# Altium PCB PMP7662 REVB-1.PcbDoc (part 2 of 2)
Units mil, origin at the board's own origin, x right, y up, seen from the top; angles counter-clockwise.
Board outline 7874.02 x 3937.01 mil, 2 copper layers (Top Layer, Bottom Layer), stack 62 mil thick; 165 components, 77 nets, 359 pads, 90 vias.
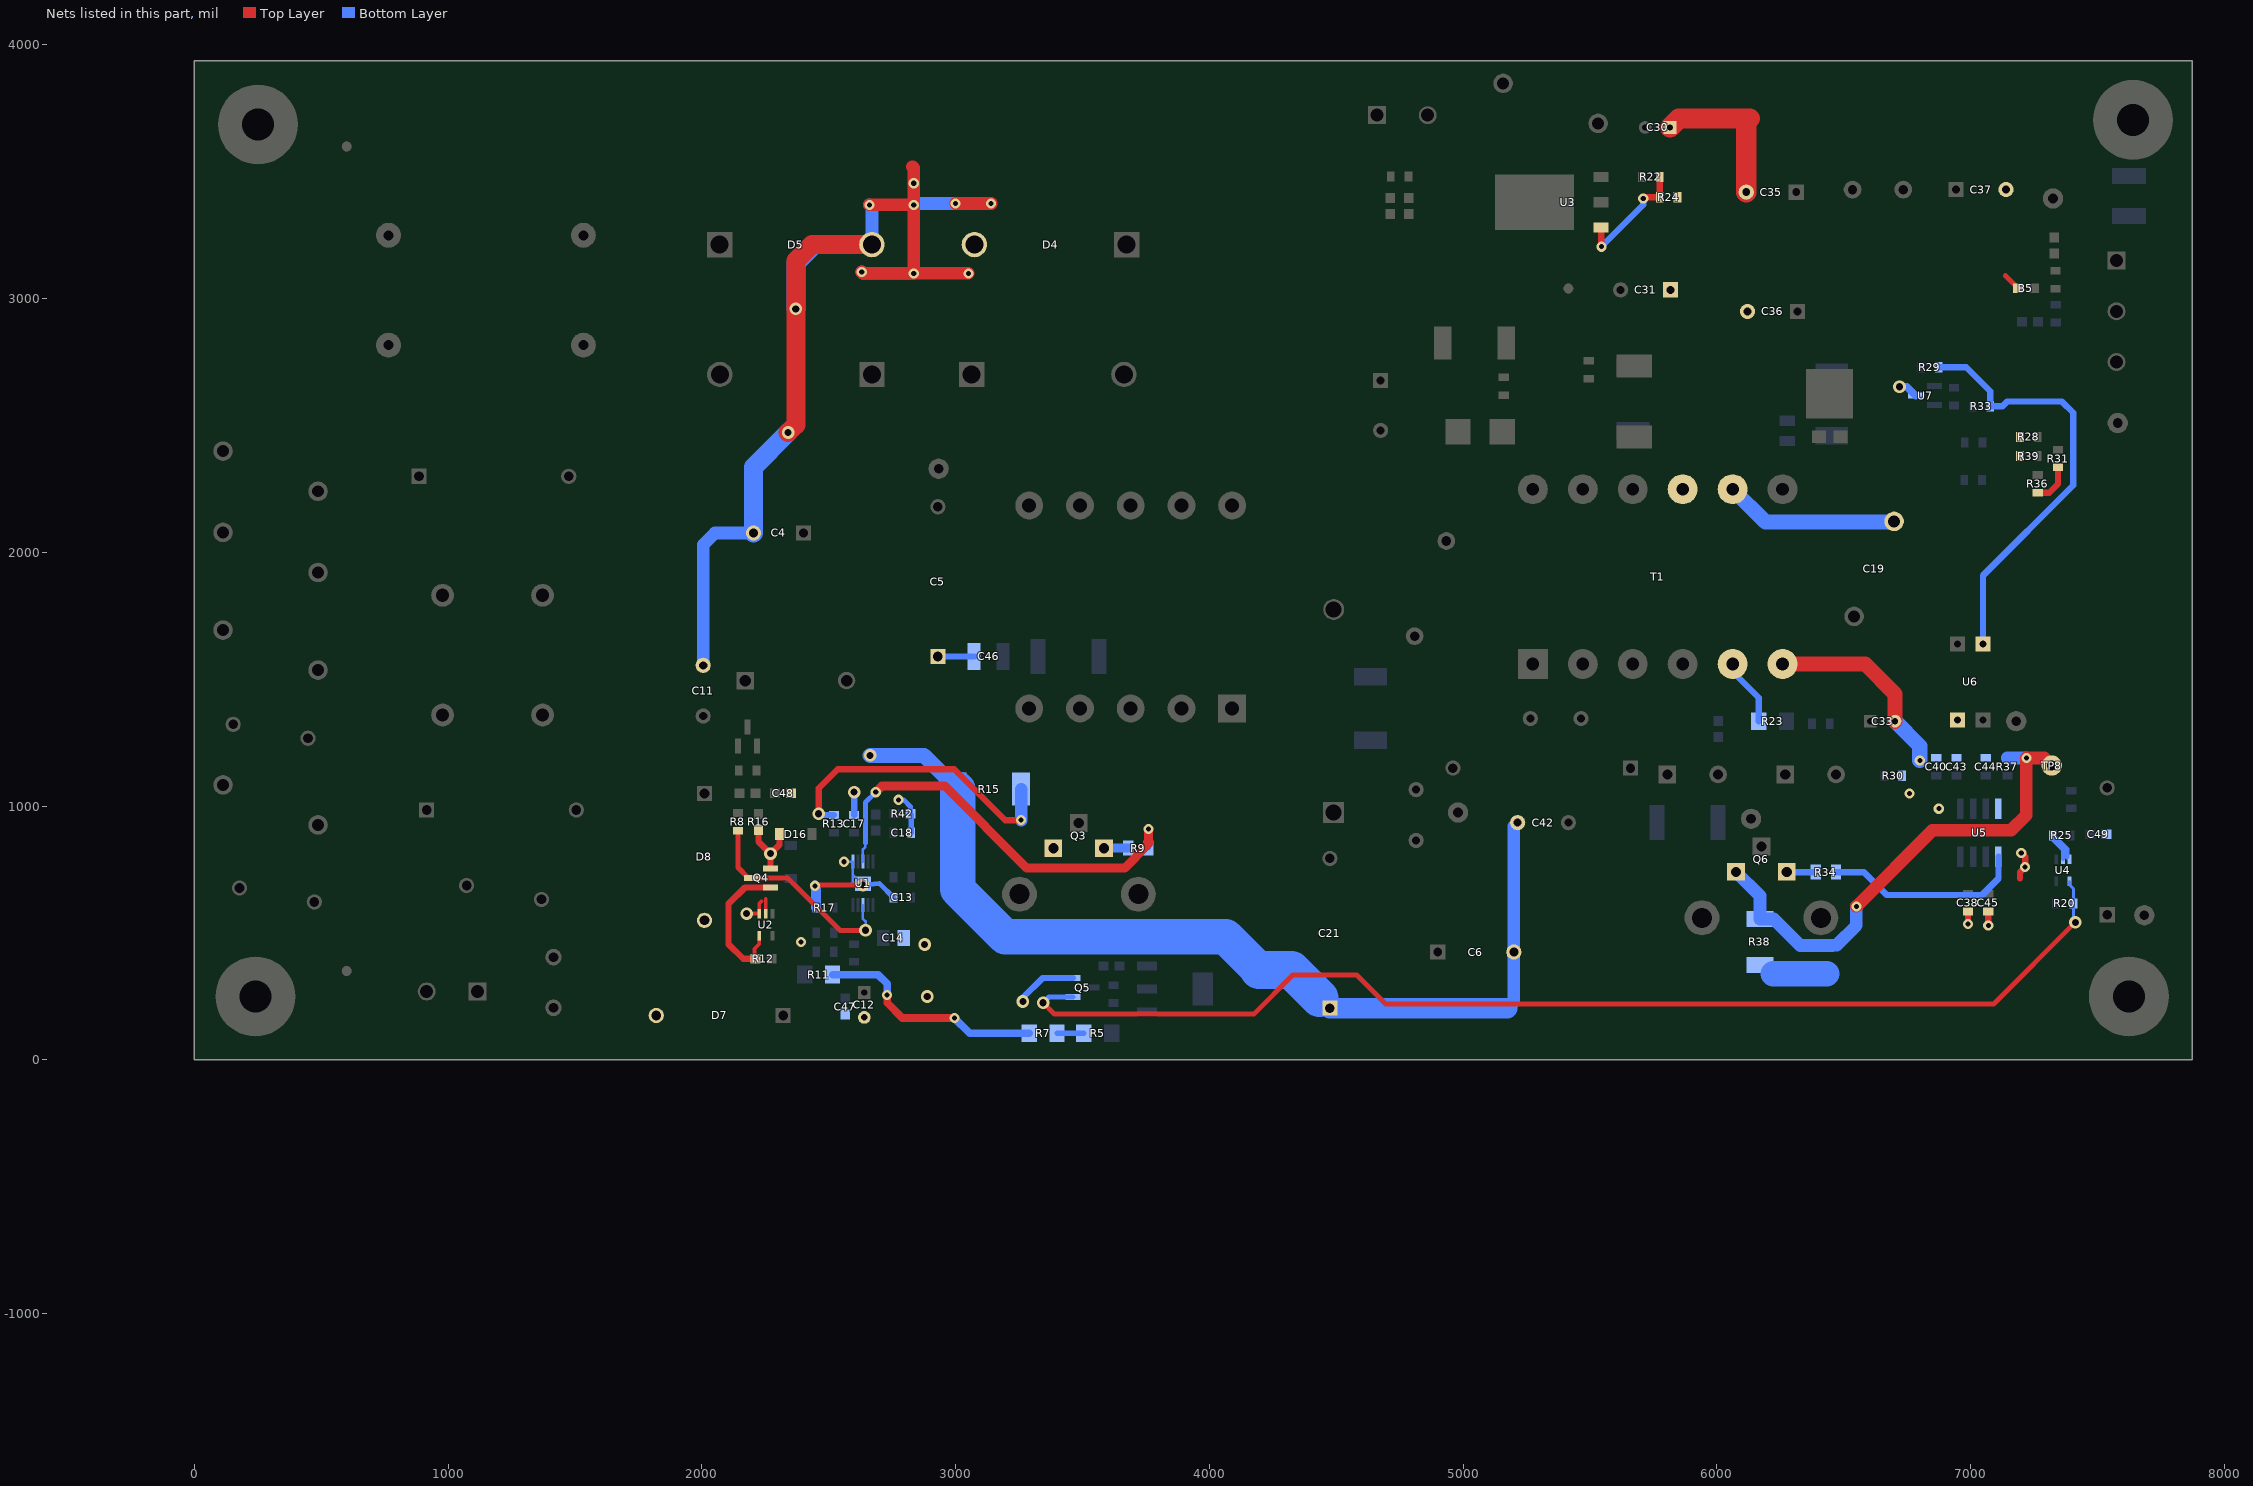
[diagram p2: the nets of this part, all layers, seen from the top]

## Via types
v1: diameter 40, hole 20, Top Layer to Bottom Layer, tented both sides, 69 vias
v2: diameter 50, hole 28, Top Layer to Bottom Layer, tented both sides, 21 vias

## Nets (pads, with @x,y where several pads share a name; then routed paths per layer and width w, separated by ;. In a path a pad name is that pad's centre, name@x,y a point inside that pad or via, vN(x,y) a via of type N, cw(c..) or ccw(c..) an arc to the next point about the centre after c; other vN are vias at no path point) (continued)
NetQ3_1: Q3.1 R9.2 | length 95.4
  Bottom Layer w35: Q3.1@3585,834.1 3585.9,835 R9.2@3680,835
NetQ3_3: Q3.3 R13.2 R15.1 | length 1196
  Top Layer w25: v2(2460,970) 2460,1070 2535,1145 2995,1145 3195,945 v1(3258,945)
  Bottom Layer w25: v2(2460,970) 2465,965 R13.2@2520,965
  Bottom Layer w50: v1(3258,945) R15.1@3258,1067
NetQ4_1: Q4.1 R12.2 U2.4 | length 578.1
  Top Layer w10: U2.4@2224.7,490.6 U2.4@2225.9,489.4
  Top Layer w15: R12.2@2207,398 2207,438 2225.9,456.9 U2.4@2225.9,489.4
  Top Layer w25: R12.2@2207,398 2163,398 2105,456 2105,615 2169.6,679.6 Q4.1@2270.4,679.6
NetQ4_3: Q4.3 R8.2 U1.3 | length 854.5
  Top Layer w20: R8.2@2142,903 2142,758 2183,717 Q4.3@2195.6,717 2338,717 2545,510 2644,510 v2(2645,511)
  Bottom Layer w10: U1.3@2634.4,610 2634.4,556 2645,545.4 v2(2645,511)
NetQ5_1: Q5.1 R20.2 U4.4 | length 4629.7
  Top Layer w20: v2(3345,225) 3390,180 4175,180 4330,335 4580,335 4695,220 7091,220 v2(7413,542)
  Bottom Layer w12: U4.4@7390.1,703.4 7390.1,689.9 7406,674 R20.2@7406,617 7406,549 v2(7413,542)
  Bottom Layer w20: v2(3345,225) 3367.6,247.6 Q5.1@3462.6,247.6
NetQ6_1: Q6.1 R34.2 | length 114.7
  Bottom Layer w25: Q6.1@6275.75,741.1 6276.85,740 R34.2@6390,740
NetQ6_3: Q6.3 R37.2 R38.1 TP8.1 | length 1987.1
  Top Layer w50: v1(6550,605) 6850,905 7160,905 7220,965 v1(7220,1190) 7290,1190 TP8.1@7320,1160
  Bottom Layer w50: Q6.3@6075.75,741.1 6170,646.85 R38.1@6170,555.55 6224.45,555.55 6328.9,451.1 6455.11,451.1 6455.74,451.73 6471.73,451.73 6550,530 v1(6550,605) ; R37.2@7145,1190 v1(7220,1190)
NetR5_2: R5.2 R7.1 | length 105
  Bottom Layer w20: R7.1@3400,105 R5.2@3505,105
NetR7_2: R7.2 R11.1 | length 914.6
  Top Layer w30: v1(2730,255) 2730,225 2790,165 v1(2995,165)
  Bottom Layer w30: R11.1@2515,336 2694,336 2730,300 v1(2730,255) ; v1(2995,165) 3055,105 R7.2@3290,105
NetR9_1: R9.1 U1.8 | length 1688.5
  Top Layer w35: v1(2685,1055) 2710,1080 2957,1080 3281,756 3666,756 3760,850 v1(3760,910)
  Bottom Layer w10: U1.8@2634.4,781 2634.4,829.4 2644,839 2644,855
  Bottom Layer w20: 2644,855 2644,1014 v1(2685,1055) ; R9.1@3760,835 v1(3760,910)
NetR22_1: R22.1 R24.1 U3.1 | length 480.8
  Top Layer w25: U3.1@5544,3280 5544,3206 v1(5545,3205) ; v1(5710,3395) 5715,3400 R24.1@5775,3400 R22.1@5775,3480
  Bottom Layer w25: v1(5545,3205) 5710,3370 v1(5710,3395)
NetR23_1: R23.1 T1.5 | length 237.5
  Bottom Layer w25: T1.5@6062.4,1530 6165,1427.4 R23.1@6165,1335
NetR29_1: R29.1 R33.1 U6.1 | length 1712.8
  Bottom Layer w25: R29.1@6875,2730 6983,2730 7078,2635 R33.1@7078,2576 7126,2576 7145,2595 7360,2595 7405,2550 7405,2265 7049,1909 U6.1@7049,1639.5
NetR31_1: R31.1 R36.1 | length 159.5
  Top Layer w25: R36.1@7265,2235 7310,2235 7345,2270 R31.1@7345,2335
NetR34_1: R34.1 U5.5 | length 790.2
  Bottom Layer w25: R34.1@6470,740 6580,740 6670,650 7045,650 7110,715 U5.5@7110,801
PGND: C4.2 C5.1 C6.2 C11.1 C12.2 C13.1 C14.2 C17.1 C18.1 C21.1 C33.2 C38.2 C40.1 C42.2 C43.2 C44.2 C45.1 C46.2 C47.2 C48.2 C49.2 D4.2 D5.2 D7.2 D8.2 D16.2 Q4.2 Q5.2 R15.2 R16.2 R17.2 R25.2 R30.2 R38.2 R42.1 T1.6 U1.6 U1.11 U2.2 U2.3 U4.2 U4.3 U5.4 U6.3 | length 11379.2
  Top Layer w15: v2(2176.4,576.4) U2.3@2225.9,576.4 2225.9,615.9 2235,625 ; U2.2@2251.9,576.4 2251.9,634.1
  Top Layer w20: v1(2445,686) 2448.5,689.5 v2(2634.8,689.5)
  Top Layer w25: R16.2@2223,903 2223,860.4 v2(2270.4,813) ; Q4.2@2270.4,754.4 v2(2270.4,813) ; D16.2@2305.53,890 2305.53,848.13 v2(2270.4,813) ; v1(6990,535) C38.2@6990,585 ; v1(7070,530) C45.1@7070,585 ; 7195,715 7195,740 v1(7215,760) 7215,800 v1(7200,815)
  Top Layer w50: v1(2630,3105) 2635,3100 v1(2835,3100) ; v1(2660,3370) v1(2835,3370) ; 2830,3520 2835,3515 v1(2835,3455) v1(2835,3370) ; v1(3000,3375) v1(3140,3375) ; v1(3050,3100) v1(2835,3100) ; v1(2835,3100) v1(2835,3370)
  Top Layer w60: T1.6@6259.25,1560 6585,1560 6702.5,1442.5 C33.2@6702.5,1335
  Top Layer w75: v2(2340,2473) 2370,2503 v2(2370,2960) 2370,3150 2433.31,3213.31 D5.2@2670,3213.31
  Bottom Layer w10: v1(2560,781) U1.6@2595,781 2595,694.5 ; 2595,729.3 v2(2634.8,689.5)
  Bottom Layer w15: U4.2@7364.1,790.4 7364.1,830.9
  Bottom Layer w20: 2595,694.5 v2(2634.8,689.5) 2700.5,694.5 C13.1@2755,640 ; 2755,1200 2775,1180 ; v1(2775,1025) 2795,1025 2821.5,998.5 R42.1@2821.5,970 2825,966.5 C18.1@2825,895 ; 7364.1,830.9 7325,870 R25.2@7325,885 7380,830 7380,800.5
  Bottom Layer w25: v2@2270,813 v2(2270.4,813) ; C17.1@2600,965 v2(2600,1055) ; C5.1@2930,1590 C46.2@3072.91,1590 ; v2@3265,245 3342.4,322.4 Q5.2@3462.6,322.4 ; v1(6875,990) v1@6875,995
  Bottom Layer w40: v1(2445,686) 2450,681 R17.2@2450,600
  Bottom Layer w50: C11.1@2005,1555 2005,2030 2051.6,2076.6 C4.2@2203.6,2076.6 ; v1(2630,3105) 2635,3100 v1(2835,3100) ; v1(2660,3370) 2670,3360 D5.2@2670,3213.31 ; v1(2835,3370) 2840,3375 v1(3000,3375) ; 5174,204 5200,230 C6.2@5200,425 5200,920 C42.2@5215,935
  Bottom Layer w60: v2(2663,1200) 2755,1200 2875,1200 R15.2@3008,1067 ; 6443.55,338.45 6448,334 ; C33.2@6702.5,1335 6800,1237.5 v1(6800,1180)
  Bottom Layer w75: C4.2@2203.6,2076.6 2203.6,2336.6 v2(2340,2473) ; v2(2370,2960) 2370,3140 2443.31,3213.31 D5.2@2670,3213.31
  Bottom Layer w80: C21.1@4475,204 5174,204
  Bottom Layer w100: 6223,340 6433.55,340
  Bottom Layer w140: R15.2@3008,1067 3008,671.78 3194.78,485 4065,485 4195,355
  Bottom Layer w150: 4195,355 4324,355 4434.5,244.5
  other v1: 2390,465 6760,1050
  other v2: 3265,230 2888,250 2878,455
PWRGND: B5.1 C19.2 C30.1 C31.1 C35.2 C36.2 C37.2 R24.2 R28.2 R39.2 T1.8 T1.9 U7.3 | length 1441.5
  Top Layer w20: 7138,3090.5 B5.1@7186.5,3042
  Top Layer w80: C30.1@5815.5,3675 5850.5,3710 6130,3710 6116,3696 C35.2@6116,3420
  Bottom Layer w30: v2(6720,2653) 6748.6,2653 U7.3@6783.6,2618
  Bottom Layer w60: T1.8@6062.4,2248.98 6191.38,2120 C19.2@6679,2120
pads on no net: FID1.1 FID2.1 FID3.1 FID4.1 FID5.1 FID6.1 H1.1 H4.1 HT1.1 HT1.2 HT2.1 HT2.2 L1.1 L1.2 L1.9 L1.10 LBL1.0 Logo1.0 T1.2 T1.3 U2.1 U4.1 U5.8

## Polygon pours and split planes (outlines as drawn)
PWRGND on Top Layer "Bottom Layer-No Net 7" (solid, pour order 101): 5800,3600 5775,3625 5775,3780 5810,3815 7085,3815 7230,3670 7230,3130 7200,3100 7200,2850 7145,2795 7150,2790 7150,2610 7225,2535 7225,1770 7155,1700 6850,1700 6775,1775 6775,2450 6650,2575 6650,3585 6585,3650 6000,3650 5950,3600
PGND on Top Layer "Top Layer-No Net 11" (solid, remove dead copper, pour order 130): 2710,1260 2775,1195 2775,1055 2815,1055 2925,945 2925,125 2895,95 1800,95 1775,120 1775,300 1955,480 1955,845 2370,1260
NetD1_2 on Top Layer "Top Layer-No Net 10" (hatched 90Degree grid 5 track 8, remove dead copper, pour order 97): 3220,1160 3170,1210 3170,1415 3195,1440 3775,1440 3790,1425 3790,1320 3810,1300 4205,1300 4255,1350 4255,1360 4252,1889.69 4282,1918.2 4306,1941 4553,1941 4586,1909.65 4604,1892.54 4604,1714.87 4559,1672.12 4554,1676.87 4425,1675 4390,1640 4390,1265 4285,1160
NetB4_1 on Top Layer "Top Layer-No Net 2" (solid, remove dead copper, pour order 70): 5515,3455 5720,3455 5730,3465 5730,3545 5730,3695 5720,3705 5690,3705 5680,3695 5680,3655 5680,3550 5675,3545 5650,3520 5545,3520 5510,3520 5505,3515 5505,3460 5510,3455 5515,3455
NetD1_2 on Top Layer "Top Layer-No Net 22" (hatched 90Degree grid 8 track 8, remove dead copper, pour order 100): 3440,1025 3520,1025 3520,920 3450,920 3450,1025
NetD2_2 on Top Layer "Top Layer-No Net 14" (solid, pour order 118): 3510,3480 3510,2530 3555,2485 4170,2485 4205,2520 4225,2540 4225,3215 4225,3495 4115,3605 4075,3645 3690,3645 3590,3645 3525,3580 3510,3565 3510,3470
PGND on Top Layer "Top Layer-No Net 13" (solid, pour order 116): 2522.28,3075.51 3210.51,3075.51 3215,3080 3210,3085 3210,3380 3210,3400 3150,3460 3125,3485 2650,3485 2545,3485 2515,3455 2522.28,3447.72 2522.28,3075.51
NetB5_2 on Top Layer "Top Layer-No Net 12" (solid, pour order 114): 7235,3075 7235,2990 7260,2965 7455,2965 7460,2970 7475,2985 7475,3025 7475,3060 7455,3080 7450,3085 7265,3085 7245,3085 7235,3075
PGND on Top Layer "Top Layer-No Net 5" (hatched 90Degree grid 5 track 8, remove dead copper, pour order 107): 6756.5,735 6762,735 6905,865 7009.5,865 7202,865 7218.5,850 7235,835 7235,675 7235,515 7163.5,450 7152.5,440 6789.5,440 6756.5,440 6740,455 6740,725 6751,725 6762,735
PGND on Top Layer "Top Layer-No Net 4" (hatched 90Degree grid 5 track 8, remove dead copper, pour order 106): 6805,950 7135,950 7150,950 7180,980 7180,1155 7180,1180 7150,1210 7135,1225 6795,1225 6775,1225 6720,1170 6715,1165 6715,1030 6715,982.48 6747.48,950 6795,950
NetC3_1 on Top Layer "Top Layer-No Net 3" (solid, pour order 103): 5130,1485 5130,1645 5165,1680 5320,1680 5325,1680 5360,1645 5355,1640 5355,1440 5355,1295 5150,1090 5070,1010 5070,920 5070,445 4995,370 4985,360 4830,360 4725,360 4515,570 4425,660 4425,990 4425,1005 4460,1040 4465,1045 4625,1045 4670,1045 4713,1002 4715,1000 4715,810 4715,785 4750,750 4755,745 4835,745 4850,745 4875,770 4875,1260 4875,1280 4905,1310 4910,1315 4955,1315 4960,1315 5130,1485
NetC35_1 on Top Layer "Bottom Layer-No Net 2" (solid, pour order 88): 6575,2525 6570,2530 6345,2530 6290,2530 6245,2575 6225,2595 6225,2780 6225,3525 6275,3575 6505,3575 6550,3575 6575,3550 6575,3380 6575,2535 6570,2530
NetC34_2 on Top Layer "Top Layer-No Net 1" (solid, pour order 85): 6209.85,2150 6331.12,2150 6530,2349.06 6530,2392.75 6530,2475.29 6520.3,2485 6389.33,2485 6224.4,2485 6205,2465.58 6209.85,2460.72 6209.85,2198.55 6209.85,2150
PWRGND on Top Layer "Top Layer-No Net" (solid, pour order 82): 5840,2145 6130,2145 6150,2165 6150,2260 6150,3450 6125,3475 5855,3475 5850,3475 5825,3450 5825,3135 5825,3130 5770,3075 5770,2960 5770,2875 5820,2825 5820,2555 5820,2365 5785,2330 5785,2195 5785,2170 5810,2145 5840,2145
NetD3_2 on Top Layer "Top Layer-No Net 10" (solid, remove dead copper, pour order 91): 1350,3463.39 1350,3221.86 1350,3192.88 1387.85,3154.23 1402.04,3139.74 1685.91,3139.74 1865.7,3139.74 1936.67,3067.28 1936.67,2869.23 1936.67,2564.52 1939.13,2562.01 1940.73,2563.64 2218.53,2563.64 2218.53,3219.8 2230,3231.52 2230,3410.25 2230,3477.88 2163.76,3545.51 2149.57,3560 1614.95,3560 1406.77,3560 1387.85,3540.68 1354.73,3506.86 1354.73,3453.73
NetC3_1 on Top Layer "Top Layer-No Net 10" (solid, remove dead copper, pour order 99): 4309,760 4650,760 4672,782 4715,825 4715,868 4715,1000 4660,1055 4639,1076 4446,1076 4385,1076 4324,1015 4311,1002 4311,768.64
NetC4_1 on Top Layer "Top Layer-No Net 10" (hatched 90Degree grid 5 track 8, remove dead copper, pour order 93): 3750.92,1990 3771.69,2015 3780,2025 3780,2310 3725.99,2375 3721.84,2380 2492.1,2380 2371.62,2235 2355,2215 2355,2005 2370,1990
PGND on Top Layer "Bottom Layer-No Net" (hatched 90Degree grid 5 track 8, remove dead copper, pour order 109): 2830,285 3290,285 3305,270 3305,215 3300,210 3295,205 3235,205 3210,205 3200,215 3160,215 2807,215 2801,221 2795,227 2795,260 2795,275 2805,285 2830,285
NetD3_2 on Top Layer "Top Layer-No Net 17" (solid, pour order 128): 1370,3055 1340,3085 1340,3095 1340,3182.88 1350,3192.88 1362.88,3180 1775,3180 1830,3180 1900,3110 1905,3105 1905,2785 1900,2785 1625,3060 1620,3055 1370,3055
NetD2_2 on Top Layer "Top Layer-No Net 18" (solid, pour order 132): 3505,3555 3505,3825 3565,3885 3570,3890 4225,3890 4235,3890 4340,3785 4340,2570.69 4340,2560 4270,2490 4265,2485 4170,2485 4105,2485 4045,2545 3865,2725 3865,3315 3745,3315 3505,3555
PGND on Top Layer "Top Layer-No Net 19" (solid, pour order 133): 2522.28,3447.72 2525,3450.43 2525,3855 2525,3875 2555,3905 3090,3905 3180,3905 3205,3880 3221.56,3863.44 3221.56,3370.79 2579.21,3370.79 2530,3420 2520,3430 2520,3470
NetD3_2 on Top Layer "Top Layer-No Net 20" (solid, pour order 134): 2230,3477.88 2230,3825 2155,3900 2150,3905 1375,3905 1355,3905 1325,3875 1340,3860 1340,3180 2210,3180 2215,3185 2230,3200 2230,3469.79
NetC4_1 on Top Layer "Top Layer-No Net 21" (solid, pour order 137): 2522.6,2562.01 2522.6,2467.4 2525,2465 2560,2500 3310,2500 3310,2847.5 3303.45,2854.05 3302.5,2855 2515.32,2855 2515.32,2539.68 2555,2500
NetD1_2 on Top Layer "Top Layer-No Net 23" (solid, pour order 75): 3370,930 3605,930 3605,1125 3605,1126 3660,1181 3655,1176 3370,1176 3310,1176 3370,1116 3370,1115
PGND on Top Layer "Top Layer-No Net 24" (solid, pour order 80): 2330,2515 2405,2515 2405,2485 2240,2320 2240,2080 2225,2065 2180,2065 2165,2080 2165,2350
NetD12_1 on Top Layer "Top Layer-No Net 25" (solid, pour order 78): 5735,2335 5785,2385 5785,2395 5785,2495 5780,2500 5760,2520 5755,2525 5600,2525 5575,2500 5575,2240 5575,2215 5600,2190 5605,2185 5700,2185 5710,2185 5735,2210
NetC27_1 on Top Layer "Top Layer-No Net 26" (solid, pour order 81): 5475,2725 5530,2725 5615,2640 5630,2640 5740,2640 5775,2675 5775,2810 5735,2850 5735,2870 5735,3100 5755,3120 5790,3155 5790,3205 5790,3360 5720,3430 5515,3430 5515,2945 5505,2935 5475,2905 5475,2880
NetD3_2 on Bottom Layer "Bottom Layer-No Net 16" (solid, remove dead copper, pour order 115): 1915,2565 2220,2565 2220,3500 2150,3570 1380,3570 1350,3540 1350,3195 1400,3145 1865,3145 1915,3095
NetD3_2 on Bottom Layer "Bottom Layer-No Net 19" (solid, remove dead copper, pour order 121): 1350,3220 1350,3105 1375,3080 1900,3080 1935,3115 1935,3180 1845,3270 1665,3270 1625,3310 1440,3310
NetD3_2 on Bottom Layer "Bottom Layer-No Net 22" (solid, pour order 127): 1615,3080 1630,3080 1950,2765 2115,2765 2115,3135 2020,3230 1615,3230
NetD2_2 on Bottom Layer "Top Layer-No Net 10" (solid, remove dead copper, pour order 92): 655,3165 690,3130 835,3130 875,3170 875,3230 1360,3715 3215,3715 3510,3420 3510,2530 3555,2485 3800,2485 3875,2560 3860,2575 3860,3580 3535,3905 1235,3905 655,3325
PGND on Bottom Layer "Bottom Layer-No Net 9" (solid, remove dead copper, pour order 105): 6705,925 6740,890 6740,200 6810,130 7195,130 7610,545 7610,1300 7515,1395 6890,1395 6705,1210
PGND on Bottom Layer "Bottom Layer-No Net" (solid, remove dead copper, pour order 102): 2495,665 2480,650 2480,590 2465,575 2425,575 2405,555 2405,410 2400,405 2355,405 2345,395 2345,280 2355,270 2505,270 2510,265 2510,205 2525,190 2735,190 2770,225 2770,490 2870,590 2870,765 2820,815 2820,995 2810,1005 2755,1005 2745,1015 2745,1050 2755,1060 2805,1060 2910,955 2910,590 2935,565 2935,130 2900,95 1790,95 1775,110 1775,300 1955,480 1955,858 2357,1260 2700,1260 2730,1230 2730,1165 2720,1155 2495,1155 2475,1135 2475,790 2545,720 2715,720 2725,710 2725,675 2715,665
PGND on Bottom Layer "Top Layer-No Net 10" (solid, remove dead copper, pour order 94): 3080,1005 3125,1050 3125,1635 3070,1690 2870,1690 2825,1645 2825,1090 2910,1005
PGND on Bottom Layer "Bottom Layer-No Net 28" (solid, pour order 140): 2635,1260 2865,1260 2880,1245 2880,1165.17 2870,1155 2635,1155 2625,1165 2625,1250
NetB6_1 on Bottom Layer "Bottom Layer-No Net 5" (solid, pour order 95): 6680,3575 6980,3575 7030,3525 7030,3000 7050,2980 7205,2980 7220,2965 7220,2870 7175,2825 6750,2825 6650,2925 6655,2930 6655,3550
NetB5_2 on Bottom Layer "Bottom Layer-No Net 15" (solid, pour order 113): 7645,2915 7700,2970 7695,3325 7675,3345 7420,3345 7380,3305 7380,3115 7300,3035 7300,2975 7315,2960 7475,2960 7520,2915
NetC7_2 on Bottom Layer "Bottom Layer-No Net 31" (solid, pour order 90): 235,515 315,435 315,215 275,175 145,175 50,270 50,2495 75,2520 205,2520 235,2490
NetD2_2 on Bottom Layer "Bottom Layer-No Net 18" (solid, pour order 119): 3555,2485 4170,2485 4225,2540 4225,3495 4075,3645 4055,3645 3590,3645 3525,3580 3515,3570 3515,3285 3515,2521.5 3551.5,2485 3555,2485
PGND on Bottom Layer "Bottom Layer-No Net 17" (solid, pour order 117): 2515,3455 2515,3085 2530,3070 3210,3070 3216.05,3070 3221.56,3075.51 3225,3078.95 3225,3385 3125,3485 2545,3485 2515,3455
NetB3_1 on Bottom Layer "Bottom Layer-No Net 14" (solid, pour order 112): 5950,1275 6055,1275 6080,1275 6100,1255 6115,1240 6115,1025 6115,1020 6165,970 6185,950 6185,905 6185,850.35 6175.75,841.1 6174.65,840 6135,840 6120,840 6090,870 5990,870 5955,870 5925,900 5920,905 5920,1250 5920,1265 5930,1275 5950,1275
NetB3_2 on Bottom Layer "Bottom Layer-No Net 13" (solid, pour order 111): 5935,1325 6055,1325 6060,1325 6070,1335 6070,1360 6070,1361.42 5960,1471.42 5960,1640 5940,1660 5925,1675 5840,1675 5800,1675 5775,1650 5775,1520 5775,1450 5885,1340 5900,1325 5925,1325
NetB6_2 on Bottom Layer "Bottom Layer-No Net 6" (solid, pour order 98): 7250,2938.54 7245,2933.54 7245,2770 7245,2705 7275,2675 7550,2675 7655,2675 7680,2700 7680,2840 7680,2845 7665,2860 7655,2870 7570,2870 7530,2870 7465,2935 7461.46,2938.54 7250,2938.54
NetC35_1 on Bottom Layer "Bottom Layer-No Net 4" (solid, pour order 89): 6310,2610 6545,2610 6550,2610 6575,2635 6570,2640 6570,2985 6570,3005 6535,3040 6320,3040 6250,3040 6225,3015 6225,2660 6225,2635 6250,2610 6315,2610
PGND on Bottom Layer "Bottom Layer-No Net 1" (solid, pour order 73): 4330,115 4555,115 4565,115 4595,145 4595,320 4595,330 4560,365 4525,400 4380,400 4290,310 4290,155 4290,154 4330,114
PGND on Bottom Layer "Top Layer-No Net 10" (solid, remove dead copper, pour order 96): 2835,1525 3080,1525 3100,1545 3100,1830 3035,1895 2270,1895 2270,2135 2240,2165 2115,2165 2090,2140 2090,1765 2110,1745 2785,1745 2825,1705 2825,1535
NetQ3_3 on Bottom Layer "Bottom Layer-No Net 23" (solid, pour order 129): 3310,870 3420,870 3420,800 3420,795 3310,795 3310,870
NetD2_2 on Bottom Layer "Bottom Layer-No Net 11" (solid, pour order 131): 3535,3905 3550,3890 4205,3890 4235,3890 4325,3800 4340,3785 4340,2965 4340,2560 4265,2485 4260,2490 4125,2490 4015,2490 3815,2690 3815,3405 3815,3480 3530,3765 3535,3770 3535,3890
NetC4_1 on Bottom Layer "Bottom Layer-No Net 24" (solid, pour order 135): 2522.6,2555 2525,2552.6 2525,2425 3220,2425 3225,2430 3225,2560 2524.61,2560 2522.6,2562.01
NetC4_1 on Bottom Layer "Bottom Layer-No Net 25" (solid, pour order 136): 3188.06,2857.28 3190.34,2855 3277.5,2855 3302.5,2855 3307.5,2850 3307.5,2430 3202.5,2430 3197.5,2425 3188.06,2434.44 3188.06,2857.28
PGND on Bottom Layer "Bottom Layer-No Net 26" (solid, pour order 138): 2515,3085 2515,3015 2515,3033.31 2523.31,3025 2785,3025 3221.69,3025 3225,3028.31 3225,3078.95
PGND on Bottom Layer "Bottom Layer-No Net 27" (solid, pour order 139): 3180,3025 3291.69,3025 3295,3028.31 3300,3033.31 3300,3315 3230,3385 3225,3385 3199,3385 3194,3390 3180,3376 3180,3030
PGND on Bottom Layer "Bottom Layer-No Net 12" (solid, pour order 110): 4375,350 4375,135 4390,120 4390,114 4899,114 4900,115 5060,115 5070,125 5070,240 5050,260 4660,260 4570,350
PGND on Bottom Layer "Bottom Layer-No Net 29" (solid, pour order 83): 2245,2325 2410,2490 2410,3140 2335,3140 2335,2520 2180,2365 2180,2325
NetC4_1 on Bottom Layer "Bottom Layer-No Net 32" (solid, pour order 74): 2345,2050 2345,2220 2350,2225 2515,2390 2515,2690 2515,2859.69 2515.32,2860 2740,2860 2808,2792 2808,2340 2808,2225 2603,2020 2375,2020
PGND on Bottom Layer "Bottom Layer-No Net 10" (hatched 90Degree grid 5 track 8, remove dead copper, pour order 108): 6300,150 6320,130 6810,130 6810,495 6705,390 6300,390
PGND on Bottom Layer "Bottom Layer-No Net 8" (hatched 90Degree grid 5 track 8, remove dead copper, pour order 104): 5125,575 5125,225 5195.33,150 5218.78,125 6226.87,125 6255,155 6255,365 6203.42,420 5504.79,420 5350,575

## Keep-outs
Keep-Out Layer:
  lines w10: 25,50 7774.02,50
  text ".Layer_Name" at 577,-858.49 h60

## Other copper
Top Layer:
  rectangle net NetD3_2: 1922.28,3075.51 2217.56,3370.79
  rectangle net NetD3_2: 1922.6,2562.01 2217.87,2857.28
  rectangle net NetC4_1: 2522.6,2562.01 2817.87,2857.28
  rectangle net PGND: 2522.28,3075.51 3215,3370.79
  rectangle net NetC4_1: 2915.28,2562.01 3210.56,2857.28
  rectangle net PGND: 2926.28,3073.82 3221.56,3369.09
  rectangle net NetD2_2: 3515.28,2562.01 3810.56,2857.28
  rectangle net NetD2_2: 3526.28,3073.82 3821.56,3369.09
  rectangle net NetD3_2: 1900,2562.01 2217.87,3405
  rectangle net PGND: 2530,3070 3210,3370
  rectangle net NetC4_1: 2515.32,2562.01 3210.56,2860
  pour cut-out: 2785,210 2785,305 2715,305 2715,210
  pour cut-out: 2325,490 2325,361.12 2313.88,350 2157.51,350 2136.25,371.25 2136.25,446.25 2151.18,461.18 2249.68,461.18 2278.5,490
  pour cut-out: 2355,550 2355,610 2335,630 2305,630 2300,625 2300,580 2330,550
  pour cut-out: 2457,839 2393,839 2387,845 2387,940 2398,951 2450,951 2464,937 2464,846
  pour cut-out: 2259,606 2259,648 2266,655 2301,655 2301,615 2291,605 2290,605 2285,600 2265,600
  region net NetC27_1: 5450,3225 5400,3175 4950,3175 4925,3200 4925,3600 5450,3600 5450,3475 5495,3430 5515,3430 5515,3325 5495,3325 5450,3280
  region net NetC1_1: 825,1380 855,1410 1080,1410 1110,1380 1110,535 955,380 955,240 935,220 845,220 825,240
  region net NetF1_1: 1075,310 1420,310 1450,280 1450,150 1420,120 1105,120 1075,150
  region net NetC1_2: 1345,370 1325,390 1325,1380 1355,1410 1540,1410 1595,1355 1595,390 1575,370
  pour cut-out: 7413,3216 7523,3216 7523,3190.31 7479.69,3190.31 7413,3188.88
  pour cut-out: 7514.88,3089.88 7455.12,3089.88 7455,3090 7455,3125 7520,3125 7520,3090 7515,3090
  pour cut-out: 6720,1870 6980,1610 6720,1610
  pour cut-out: 3450,930 3370,1010 3370,930
  pour cut-out: 3520,930 3605,1015 3605,930
  text ".Layer_Name" at 577,-858.49 h60
Bottom Layer:
  rectangle net NetD3_2: 1922.6,2570 2220,2858.98
  rectangle net NetQ3_3: 3207,795 3332,1138
  rectangle net NetD3_2: 1922.28,3075.51 2217.56,3370.79
  rectangle net PGND: 2522.28,3075.51 2817.56,3370.79
  rectangle net NetC4_1: 2522.6,2563.7 2817.87,2858.98
  rectangle net PGND: 2926.28,3075.51 3221.56,3370.79
  rectangle net NetC4_1: 2915.28,2563.7 3210.56,2858.98
  rectangle net NetD2_2: 3526.28,3075.51 3821.56,3370.79
  rectangle net NetD2_2: 3515.28,2563.7 3810.56,2858.98
  rectangle net NetD2_2: 3540,2530 3845,3415
  rectangle net PGND: 2550,3070 3210,3365
  rectangle net NetC4_1: 2522.6,2555 3215,2857.28
  pour cut-out: 2399,970 2399,839 2375,815 2324.41,815 2301,838.41 2301,970
  pour cut-out: 2399,758 2399,644 2375,620 2324.41,620 2301,643.41 2301,758
  region net PGND: 3040,1665 3055,1650 3055,1535 3040,1520 2910,1520 2895,1535 2895,1650 2910,1665
  region net NetC46_1: 3335,1670 3350,1655 3350,1540 3335,1525 3195,1525 3180,1540 3180,1655 3195,1670
  region net NetC2_1: 945,2870 700,2870 685,2855 685,2715 755,2645 755,1815 790,1780 1015,1780 1050,1815 1050,2765
  region net NetC2_2: 1325,2870 1575,2870 1595,2850 1595,1815 1560,1780 1335,1780 1300,1815 1300,2845
  pour cut-out: 1435,3570 1445,3560 1354.73,3469.73 1354.73,3453.73 1351.27,3453.73 1310,3495 1325,3510 1325,3570
  pour cut-out: 1340,3430.49 1340.49,3430.49 1495,3585 1340,3585
  pour cut-out: 7445,930 7445,1030 7440,1035 7405,1035 7405,940 7415,930
  text ".Layer_Name" at 577,-858.49 h60

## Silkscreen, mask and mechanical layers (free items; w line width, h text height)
Top Overlay:
  text "This document can handle board shapes up to 7.9in x 10in, although" at 6380,6195 h60
  text "our panel vendors top out at 7in x 10in." at 6380,6070.94 h60
  text "To re-size the board shape, do the following:" at 6435,5946.88 h60
  text "Select lines on M1 Board Outline and delete (easy in single layer mode...shift+s)" at 6495,5822.82 h60
  text "Draw a rectangle using lines (example will be for a 4\" x 6\" board" at 6495,5698.76 h60
  text "Enter Place Line mode (keyboard pl)" at 6705,5574.71 h60
  text "keyboard jo to jump to origin, hit enter" at 6705,5450.65 h60
  text "keyboard jl to jump to location, set x to 6000, hit enter twice" at 6705,5326.59 h60
  text "keyboard jl to jump to location, set x to 6000 and y to 4000, hit enter twice" at 6705,5202.53 h60
  text "keyboard jl to jump to location, set x to 0 and y to 4000, hit enter twice" at 6705,5078.47 h60
  text "keyboard jo to jump to origin, hit enter" at 6705,4954.41 h60
  text "Hit ESC twice to exit place line mode" at 6705,4830.35 h60
  text "Select lines on M1 Board Outline" at 6495,4686.3 h60
  text "Menu Design|Board Shape|Define from Selected Objects (keyboard dsd)" at 6495,4582.24 h60
  text "To define a Keep-Out that mirrors the board outline:" at 6380,4458.18 h60
  text "Menu Design|Board Shape|Create Primitives From Board Shape (keyboard dsp)" at 6495,4334.12 h60
  text "Set the Keep-Out Layer as the layer, set width as preferred" at 6705,4210.06 h60
  text "Ensure Route Tool Outline is selected, hit enter" at 6705,4086 h60
  text "If you re-size the board, don't forget to move the drill table strings on the" at 6380,3763 h60
  text "Drill Drawing Layer...they should be just to the right of your board shape" at 6573,3657 h60
Bottom Overlay:
  text ".PRJ_Number" at 2531,335 h60
  text "-" at 1930,324.5 h60
  text ".PCB_Rev" at 1108,160 h60
  text ".Layer_Name" at 577,-858.49 h60
Top Paste:
  text ".Layer_Name" at 577,-858.49 h60
Bottom Paste:
  text ".Layer_Name" at 577,-858.49 h60
Top Solder:
  text ".Layer_Name" at 577,-858.49 h60
  text ".Layer_Name" at 577,-858.49 h60
Bottom Solder:
  text ".Layer_Name" at 577,-858.49 h60
Drill Guide:
  text ".Layer_Name" at 577,-858.49 h60
M1 Board Outline:
  the board outline again, w10
  text ".Layer_Name" at 565,-865 h60
M2 Board Dimensions:
  rectangle: 124.5,-410.5 499.5,-285.5
  rectangle: -0.5,-285.5 124.5,-160.5
  lines w7: -0.5,-285.5 999.5,-285.5 ; 124.5,-410.5 124.5,-160.5 ; 249.5,-410.5 249.5,-160.5 ; 499.5,-410.5 499.5,-160.5 ; 749.5,-410.5 749.5,-160.5 ; -0.5,-410.5 -0.5,-160.5 999.5,-160.5 999.5,-410.5 -0.5,-410.5
  lines w10: -0.5,-475.5 -0.5,-455.5 ; 59.5,-485.5 -0.5,-465.5 ; 59.5,-445.5 -0.5,-465.5 ; 223.58,-465.5 -0.5,-465.5 ; 775.42,-465.5 999.5,-465.5 ; 939.5,-485.5 999.5,-465.5 ; 939.5,-445.5 999.5,-465.5 ; 999.5,-475.5 999.5,-455.5
  text "1000 (mil)" at 233.58,-501.49 h60
  text ".Layer_Name" at 577,-858.49 h60
M3 3D STEP Top:
  text ".Layer_Name" at 577,-858.49 h60
M4 3D STEP Bottom:
  text ".Layer_Name" at 577,-858.49 h60
M5 Assembly Top:
  circle w5: c7439.38,3325 r20.62
  circle w6: c7580,2510 r55
  circle w5: c6135,950 r50.25
  circle w5: c7320,1160 r50.25
  circle w5: c7685,570 r50.25
  circle w5: c7180,1335 r50.25
  rectangle: 3205,3755 3405,3860
  lines w6: 1870,725 1930,725 ; 1900,665 1900,700 ; 1900,760 1900,725 ; 2015,295 2045,295 ; 2045,325 2045,265 2080,300 2110,300 ; 2065,1125 2110,1080 ; 2080,275 2080,330 ; 2260,995 2270.99,1005.99 2309,1005.99 ; 5585,1260 5615,1260 ; 5650,1240 5650,1295 ; 5680,1265 5650,1265 ; 7675,815 7745,815 ; 7705,855 7705,895 ; 7710,780 7710,815 7670,855 7740,855 ; 1900,725 1925,700 1875,700 1900,725 ; 5650,1265 5615,1300 5615,1230 5650,1265
  lines w10: -292,-930.17 6308,-930.17 ; -292,-726.83 6310,-726.83 ; -292,-523.5 -292,-1133.5 3713,-1133.5 6310,-1133.5 6310,-523.5 -291.5,-523.5 -291.5,-1133.5 1284,-1133.5 ; 2173,-1133.5 2173,-523.5 ; 3440,-726.83 3440,-523.5 ; 4280,-726.83 4280,-523.5 ; 4902,-1140 4902,-937.17
  text "TIDA-00127-PRPS" at 2310,3785 h60
  text "ISE3011" at 2320,3665 h60
  text "*" at 4465,3625 h40
  text "*" at 5610,3270 h40
  text "*" at 7125,1625 h40
  text "*" at 6410,715 h40
  text "*" at 1555,251 h40
  text "COMPONENTS MARKED 'DNP' SHOULD NOT BE POPULATED." at 1153.5,-318.5 h60
  text "ASSEMBLY VARIANT:" at 1153,-434 h60
  text ".VariantName" at 2189,-434 h60
  text "PCB VIEWED FROM TOP SIDE" at -228.5,-655.67 h60
  text "BOARD #:" at 2248,-655.67 h60
  text ".PRJ_Number" at 2793.5,-655.67 h60
  text "REV:" at 3638,-655.67 h60
  text ".PCB_Rev" at 3929.5,-655.67 h60
  text "SVN REV:" at 4476,-655.67 h60
  text ".VersionControl_RevNumber" at 4982,-655.67 h60
  text "Top Overlay" at 577,-858.49 h60
  text "TIDA-00127-PRPS" at 2415,-865 h60
  text "Top Overlay" at 565,-1060 h60
  text "PLOT NAME =" at -228.5,-1064.34 h60
  text "GENERATED    :" at 2250,-1064.34 h60
  text ".Print_Date" at 3119.5,-1064.34 h60
  text ".Print_Time" at 3848.5,-1064.34 h60
  text "TEXAS INSTRUMENTS" at 5113,-1064.34 h60
M6 Assembly Bottom:
  circle w6: c6880,2680 r5
  circle w6: c6880,1040 r20
  circle w6: c3420,235 r5
  text "Bottom Overlay" at 575,-865 h60
M7 LPKF Text Top:
  lines w10: -292.5,-727.33 6309.5,-727.33 ; -290.5,-930.67 6309.5,-930.67 ; 1115.5,-1140.5 1115.5,-937.67 ; 1737.5,-727.33 1737.5,-524 ; 2577.5,-727.33 2577.5,-524 ; 3844.5,-1134 3844.5,-524 ; 4733.5,-1134 6309,-1134 6309,-524 -292.5,-524 -292.5,-1134 2304.5,-1134 6309.5,-1134 6309.5,-524
  text "COMPONENTS MARKED 'DNP' SHOULD NOT BE POPULATED." at 6102,-318 h60
  text ".VariantName" at 5058,-434 h60
  text "ASSEMBLY VARIANT:" at 6097,-434 h60
  text ".VersionControl_RevNumber" at 1035.5,-656.17 h60
  text "SVN REV:" at 1541.5,-656.17 h60
  text ".PCB_Rev" at 2088,-656.17 h60
  text "REV:" at 2379.5,-656.17 h60
  text ".PRJ_Number" at 3224,-656.17 h60
  text "BOARD #:" at 3769.5,-656.17 h60
  text "Bottom Overlay" at 5640.5,-854.84 h60
  text "TIDA-00127-PRPS" at 3275,-860 h60
  text "TEXAS INSTRUMENTS" at 904.5,-1064.84 h60
  text ".Print_Time" at 2169,-1064.84 h60
  text ".Print_Date" at 2898,-1064.84 h60
  text "GENERATED    :" at 3767.5,-1064.84 h60
  text "Bottom Overlay" at 5440.5,-1064.84 h60
  text "PLOT NAME =" at 6246,-1064.84 h60
M9 Title Sheet:
  drawing of 57 lines, arcs and shapes, not listed
  text "1" at 739.84,8036.5 h70
  text "2" at 3235.5,8036.5 h70
  text "3" at 5724.84,8036.5 h70
  text "4" at 8231.51,8036.5 h70
  text "5" at 10730.5,8036.5 h70
  text "6" at 13235.5,8036.5 h70
  text "A" at -416.5,6893.5 h70
  text "A" at 14383.5,6893.5 h70
  text "B" at -416.5,4513.5 h70
  text "B" at 14383.5,4513.5 h70
  text "C" at -416.5,2138.5 h70
  text "C" at 14383.5,2138.5 h70
  text "PROJECT TITLE:" at 11343.5,277.5 h45
  text "TIDA-00127-PRPS" at 11393.5,144.17 h70
  text "DESIGNED FOR:" at 11343.5,-23.5 h45
  text ".PRJ_Customer" at 11393.5,-163.5 h70
  text "D" at -416.5,-231.5 h70
  text "D" at 14383.5,-231.5 h70
  text "FILE NAME:" at 11343.5,-323.5 h45
  text "TIDA-00127-PRPS" at 11393.5,-443.5 h70
  text "Texas Instruments (TI) and/or its licensors do not warrant the accuracy or completeness of this specification" at 6374,-605.34 h45
  text "ENGINEER:" at 11343.5,-613.5 h45
  text "LAYOUT BY:" at 12848.5,-613.5 h45
  text "or any information contained therein. TI and/or its licensors do not warrant that this design will meet" at 6329.01,-718 h45
  text "Sunil D" at 11393.5,-768.49 h70
  text ".PCB_Layout" at 12899,-768.49 h70
  text "the specifications, will be suitable for your application or fit for any particular purpose, or will operate in" at 6329.01,-830.67 h45
  text "ALTIUM DESIGNER VERSION:" at 12848.5,-923.5 h45
  text "an implementation. TI and/or its licensors do not warrant that the design is production worthy. You should" at 6329.01,-943.33 h45
  text "completely validate and test your design implementation to confirm the system functionality for your application." at 6374,-1056 h45
  text ".print_Scale" at 11393.5,-1056.83 h70
  text ".Application_BuildNumber" at 12899,-1056.83 h70
  text "1" at 739.84,-1263.5 h70
  text "2" at 3235.5,-1263.5 h70
  text "3" at 5724.84,-1263.5 h70
  text "4" at 8231.51,-1263.5 h70
  text "5" at 10730.5,-1263.5 h70
  text "6" at 13235.5,-1263.5 h70
M10 Fab Notes:
  drawing of 212 lines, arcs and shapes, not listed
  text "DESIGN INFORMATION" at 12381.02,6810 h60
  text "(REFER ALSO ARRAY/PANEL PROFILING INFORMATION)" at 12019.46,6648.29 h60
  text "BOARD SIZE" at 11333.46,6644 h60
  text "7874.02MIL" at 11735,6520 h60
  text "3937.01MIL" at 12465,6520 h60
  text "X" at 12301.46,6516.18 h60
  text "Number of Layers :" at 11736.46,6319 h60
  text "2" at 12831.27,6309 h60
  text "MIN. TRACK WIDTH:" at 11736.46,6180 h60
  text "8" at 12832.7,6180 h60
  text "MIL" at 12987.46,6180 h60
  text "MIN. CLEARANCE:" at 11736.46,6048 h60
  text "8" at 12832.7,6048 h60
  text "MIL" at 12987.46,6048 h60
  text "MIN. VIA PAD SIZE:" at 11736.46,5916 h60
  text "24" at 12802.71,5916 h60
  text "MIL" at 12987.46,5916 h60
  text "0.05mm (2MIL)" at 12431.46,5774.29 h60
  text "MINIMUM ANNULAR RING" at 11407.23,5770 h60
  text "EXTERNAL" at 13139.46,5770 h60
  text "PER" at 11607.23,5652 h60
  text "IPC-D-275 CLASS 2 LEVEL C" at 11827.23,5652 h60
  text "MIL, HOLES" at 13315.46,5539.71 h60
  text "+/-" at 12923,5539 h60
  text "+/-" at 13777,5539 h60
  text "REGISTRATION TOLERANCES:" at 11407.23,5534 h60
  text "METAL" at 12607,5534 h60
  text "5" at 13183.2,5534 h60
  text "3" at 14016.2,5534 h60
  text "MIL" at 14132.46,5534 h60
  text "MATERIAL:" at 11332.46,5324.54 h60
  text "FR-4 High Tg" at 12318.9,5184.21 h60
  text "FR-408" at 11753.46,5175.64 h60
  text "X" at 12165.46,5175.64 h60
  text "OTHER" at 13241.46,5175.64 h60
  text "62 MIL (1.6mm) +/-10%" at 12073.56,5012.92 h60
  text "THICKNESS:" at 11407.23,5008.64 h60
  text "X" at 11945.4,5008.64 h60
  text "OTHER" at 13358.46,5008.64 h60
  text "TOLERANCE:" at 11407.23,4850.64 h60
  text "X" at 12246.53,4850.64 h60
  text "ANSI IPC-6012 TYPE 3 CLASS 2" at 12433.48,4850.64 h60
  text "OTHER +/-" at 12433.46,4694.64 h60
  text "BOW & TWIST:" at 11407.23,4537.64 h60
  text "X" at 12246.53,4537.64 h60
  text "ANSI IPC-6012 TYPE 3 CLASS 2" at 12433.48,4537.64 h60
  text "OTHER +/-" at 12433.46,4379.13 h60
  text "COPPER THICKNESS (FINISHED):" at 11332.46,4243.64 h60
  text "1.4MIL (1oz)" at 12212.46,4090.92 h60
  text "2MIL (1.4oz)" at 12979.46,4090.92 h60
  text "2.8MIL (2oz)" at 13706.46,4090.92 h60
  text "OUTER:" at 11689.46,4086.64 h60
  text "X" at 12084,4086 h60
  text "1.4MIL (1oz)" at 12212.46,3933.92 h60
  text "2.8MIL (2oz)" at 12979.46,3933.92 h60
  text "N/A" at 13706,3934.29 h60
  text "INNER SIGNAL:" at 11400.38,3929.64 h60
  text "DRILLING:" at 11332.46,3790.64 h60
  text "REFERENCE:" at 11407.23,3673.64 h60
  text "X" at 12055.46,3673.64 h60
  text "AS SHOWN" at 12242.46,3673.64 h60
  text "X" at 12956.46,3673.64 h60
  text "NC_DRILL FILES" at 13093.46,3673.64 h60
  text "PTH MIN COPPER THICKNESS:" at 11407.23,3515.64 h60
  text "X" at 12757.46,3515.64 h60
  text "1MIL" at 12894.46,3515.64 h60
  text "OTHER" at 13391.46,3515.64 h60
  text "BOARD FINISH:" at 11332.46,3356.64 h60
  text "SILKSCREEN:" at 11487.68,3238.64 h60
  text "X" at 12436.46,3238.64 h60
  text "TOP" at 12562.46,3238.64 h60
  text "X" at 12946.46,3238.64 h60
  text "BOTTOM" at 13073.46,3238.64 h60
  text "SILKSCREEN COLOR:" at 11487.68,3071.64 h60
  text "X" at 12435.42,3071.64 h60
  text "WHITE" at 12562.46,3071.64 h60
  text "OTHER" at 13073.46,3071.64 h60
  text "SOLDER RESIST COLOR:" at 11487.68,2901.64 h60
  text "X" at 12055.42,2742.44 h60
  text "GREEN" at 12182.46,2742.44 h60
  text "BLUE" at 12773.46,2742.44 h60
  text "OTHER" at 13311.46,2742.44 h60
  text "IMMERSION GOLD (ENIG)" at 12393.46,2553.92 h60
  text "ENEPIG" at 13731,2550.64 h60
  text "SURFACE FINISH:" at 11332.46,2549.64 h60
  text "X" at 12206.51,2549.64 h60
  text "IMM. TIN/SILVER OR EQUIV" at 11662,2392.64 h60
  text "OTHER" at 13093.46,2392.64 h60
  text "ARRAY/PANEL:" at 11332.46,2213.64 h60
  text "CUT AND TRIM PER MECH LAYER 1" at 12393.46,2209.35 h60
  text "N.C. ROUTE" at 12393.46,2057.64 h60
  text "X" at 13072.46,2057.64 h60
  text "V. SCORE" at 13259.46,2057.64 h60
  text "CERTIFICATION:" at 11332.46,1920.64 h60
  text "MATERIALS AND WORKMANSHIP FOR ALL PCBS" at 12057.46,1920.64 h60
  text "TO MEET OR EXCEED THE REQUIREMENTS OF:" at 12057.46,1822.64 h60
  text "X" at 11683.96,1686.13 h60
  text "ANSI IPC-A-600F CLASS ->" at 11822.96,1686.13 h60
  text "X" at 13462.02,1686.13 h60
  text "2" at 13580.96,1686.14 h60
  text "1" at 13265.96,1684.64 h60
  text "3" at 13934.96,1684.64 h60
  text "X" at 11686.02,1526.64 h60
  text "UL 94V-0" at 11822.96,1526.64 h60
  text "X" at 12498.02,1526.64 h60
  text "RoHS" at 12634.96,1526.64 h60
  text "OTHER" at 13279.36,1526.64 h60
  text "PER ORDER" at 13676.42,1526.64 h60
  text "ADDITIONAL REQUIREMENTS:" at 11332.46,1385.64 h60
  text "MICROSECTION:" at 11407.23,1270.64 h60
  text "YES" at 12312.96,1270.64 h60
  text "REQUIRED" at 13174.46,1114.49 h60
  text "BARE BOARD ELEC. TEST:" at 11407.23,1111.64 h60
  text "NONE" at 12712.96,1111.64 h60
  text "X" at 13047.46,1111.64 h60
  text "PER ORDER" at 13766.46,1111.64 h60
  text "MANUFACTURER'S UL:" at 11407.23,954.64 h60
  text "RAIL" at 12572.96,950.35 h60
  text "METAL" at 13064.77,950.35 h60
  text "X" at 13440,950 h60
  text "SILK" at 13576.46,950.35 h60
M11 Gerber Information:
  lines w10: -292,-930.17 6308,-930.17 ; -292,-726.83 6310,-726.83 ; -292,-523.5 -292,-1133.5 3713,-1133.5 6310,-1133.5 6310,-523.5 -291.5,-523.5 -291.5,-1133.5 1284,-1133.5 ; 2173,-1133.5 2173,-523.5 ; 3440,-726.83 3440,-523.5 ; 4280,-726.83 4280,-523.5 ; 4902,-1140 4902,-937.17
  text "BOARD #:" at 2205,-655 h60
  text ".Rev-A1" at 3885,-655 h60
  text "ALL ARTWORK VIEWED FROM TOP SIDE" at -228.5,-655.67 h60
  text "REV:" at 3638,-655.67 h60
  text "SVN REV:" at 4476,-655.67 h60
  text ".VersionControl_RevNumber" at 4982,-655.67 h60
  text ".PRJ_Number" at 2670,-660 h60
  text "LAYER NAME =" at -228.5,-858.49 h60
  text "TIDA-00127-PRPS" at 2415,-860 h60
  text "PLOT NAME =" at -228.5,-1064.34 h60
  text ".plot_File_Name" at 577,-1064.34 h60
  text "GENERATED    :" at 2250,-1064.34 h60
  text ".Print_Date" at 3119.5,-1064.34 h60
  text ".Print_Time" at 3848.5,-1064.34 h60
  text "TEXAS INSTRUMENTS" at 5113,-1064.34 h60
M12 Stackup:
  lines w6: 11360,7460 13910,7460 ; 11360,7564.4 13910,7564.4 ; 11300,6975 ccw(c11334,6975) 11334,6941 13936,6941 ccw(c13936,6975) 13970,6975 13970,7681 ccw(c13936,7681) 13936,7715 11334,7715 ccw(c11334,7681) 11300,7681 11300,6975
  text "The Stackup Legend below this is static." at 11605.5,7874.5 h60
  text "If you change the stackup, update the Legend." at 11615.5,7784.5 h60
  text "Layer Stack Up Detail for: Ref_Design.PcbDoc" at 11360,7597.1 h57
  text "Layer" at 11360,7525.4 h24
  text "Gerber" at 12255.81,7525.4 h24
  text "Copper" at 12819.33,7525.4 h24
  text "Dielectric" at 13422.04,7525.4 h24
  text "Name" at 11360,7477.4 h24
  text "Document" at 12255.81,7477.4 h24
  text "Thickness" at 12819.33,7477.4 h24
  text "Material" at 13422.04,7477.4 h24
  text "Top Solder Mask" at 11360,7384.44 h34
  text "(.GTS)" at 12255.81,7384.44 h34
  text "Solder Resist" at 13422.04,7384.44 h34
  text "Top Layer" at 11360,7287.69 h34
  text "(.GTL)" at 12255.81,7287.69 h34
  text "1.4mil" at 12819.33,7287.69 h34
  text "FR-4" at 13422.04,7239.31 h34
  text "Bottom Layer" at 11360,7190.94 h34
  text "(.GBL)" at 12255.81,7190.94 h34
  text "1.4mil" at 12819.33,7190.94 h34
  text "Bottom Solder Mask" at 11360,7094.19 h34
  text "(.GBS)" at 12255.81,7094.19 h34
  text "Solder Resist" at 13422.04,7094.19 h34
M13 Component Bodies Top:
  text ".Layer_Name" at 577,-858.49 h60
M14 Component Bodies Bottom:
  text ".Layer_Name" at 577,-858.49 h60
M15 Courtyards Top:
  text ".Layer_Name" at 577,-858.49 h60
M16 Courtyards Bottom:
  text ".Layer_Name" at 577,-858.49 h60
Drill Drawing:
  text ".legend" at 4950,4190 h60
  text "Drill Table" at 5030,4035 h60
  text ".Layer_Name" at 577,-858.49 h60

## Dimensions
7640,3705 to 7874.02,3937.01 on M2 Board Dimensions
7640,3705 to 7874.02,3937.01 on M2 Board Dimensions
250,3687.01 to 0,3937.01 on M2 Board Dimensions
0,0 to 7874.02,0 on M2 Board Dimensions
0,0 to 0,3937.01 on M2 Board Dimensions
